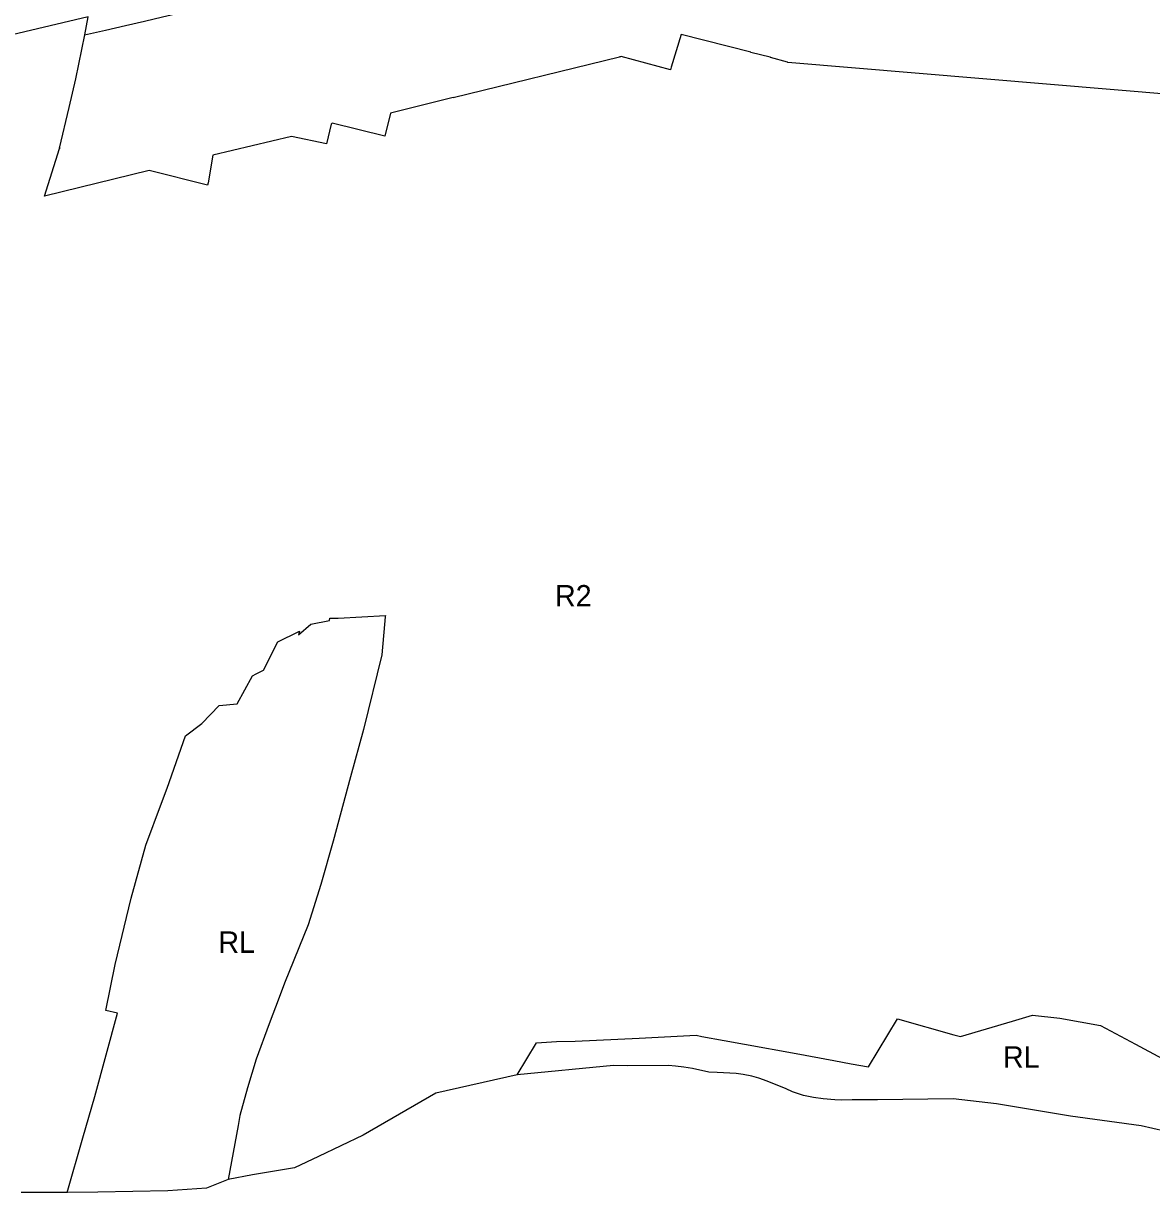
# Model space of a CAD drawing. Extents: x 7413438 to 7416393, y 5541665 to 5544118.
# Drawn here: x 7414625.9 to 7414942.1, y 5541689.3 to 5542017 of the extents above; entities that cross this region are included whole.
import ezdxf

# ---------------------------------------------------------------- set-up
doc = ezdxf.new("R2010")
doc.units = 0
for name, color, linetype in [('linie_rozgraniczajace', 7, 'Continuous'), ('linie_zabudowy_nieprzekraczalne', 7, 'Continuous'), ('oznaczenia_przeznaczen', 7, 'Continuous')]:
    doc.layers.add(name, color=color, linetype=linetype)

msp = doc.modelspace()

# ---------------------------------------------------------------- linework, layer by layer
at = {"layer": 'linie_rozgraniczajace'}
for p, q in [((7414644.1, 5542018.75), (7414622.76, 5542013.76)), ((7414643.15, 5542013.74), (7414644.1, 5542018.75)), ((7414640.59, 5542001.38), (7414643.15, 5542013.74)), ((7414810.29, 5542013.88), (7414807.46, 5542004.7)), ((7414829.75, 5542008.86), (7414810.29, 5542013.88)), ((7414829.81, 5542008.81), (7414829.75, 5542008.86)), ((7414835.19, 5542007.45), (7414829.81, 5542008.81)), ((7414792.96, 5542007.51), (7414746.39, 5541996.13)), ((7414792.97, 5542007.55), (7414792.96, 5542007.51)), ((7414793.21, 5542007.6), (7414792.97, 5542007.55)), ((7414793.42, 5542007.64), (7414793.21, 5542007.6)), ((7414807.26, 5542003.9), (7414793.42, 5542007.64)), ((7414835.27, 5542007.5), (7414835.19, 5542007.45)), ((7414835.25, 5542007.42), (7414835.27, 5542007.5)), ((7414840.03, 5542006.08), (7414835.25, 5542007.42)), ((7414840.1, 5542005.99), (7414840.03, 5542006.08)), ((7414952.51, 5541996.58), (7414840.1, 5542005.99)), ((7414807.46, 5542004.7), (7414807.26, 5542003.9)), ((7414638.8, 5541993.41), (7414640.59, 5542001.38)), ((7414746.36, 5541996.17), (7414728.8, 5541991.78)), ((7414746.39, 5541996.13), (7414746.36, 5541996.17)), ((7414636.1, 5541982.01), (7414638.8, 5541993.41)), ((7414712.48, 5541988.95), (7414712.21, 5541988.7)), ((7414727.19, 5541985.33), (7414712.48, 5541988.95)), ((7414728.8, 5541991.78), (7414727.2, 5541985.38)), ((7414712.21, 5541988.7), (7414710.84, 5541983.2)), ((7414701.02, 5541985.22), (7414679.04, 5541979.99)), ((7414710.84, 5541983.2), (7414701.02, 5541985.22)), ((7414727.2, 5541985.38), (7414727.19, 5541985.33)), ((7414631.88, 5541968.55), (7414636.08, 5541981.92)), ((7414636.08, 5541981.92), (7414636.23, 5541981.98)), ((7414636.23, 5541981.98), (7414636.1, 5541982.01)), ((7414679.04, 5541979.99), (7414677.72, 5541972.23)), ((7414661.15, 5541975.72), (7414631.88, 5541968.55)), ((7414677.54, 5541971.6), (7414661.15, 5541975.72)), ((7414677.72, 5541972.23), (7414677.54, 5541971.6)), ((7414703.06, 5541845.58), (7414706.46, 5541848.54)), ((7414706.46, 5541848.54), (7414711.7, 5541849.6)), ((7414711.7, 5541849.6), (7414711.82, 5541850.21)), ((7414711.82, 5541850.21), (7414714.11, 5541850.3)), ((7414714.11, 5541850.3), (7414727.38, 5541851.03)), ((7414727.09, 5541848.49), (7414726.34, 5541839.99)), ((7414727.28, 5541850.6), (7414727.09, 5541848.49)), ((7414727.38, 5541851.03), (7414727.28, 5541850.6)), ((7414697.25, 5541843.58), (7414703.16, 5541846.48)), ((7414703.3, 5541846.57), (7414703.06, 5541845.58)), ((7414703.16, 5541846.48), (7414703.3, 5541846.57)), ((7414693.22, 5541835.69), (7414697.25, 5541843.58)), ((7414726.34, 5541839.99), (7414721.22, 5541819.07)), ((7414691.13, 5541834.62), (7414693.22, 5541835.69)), ((7414685.88, 5541826.22), (7414690.15, 5541834.12)), ((7414690.15, 5541834.12), (7414691.13, 5541834.62)), ((7414675.97, 5541820.75), (7414680.83, 5541825.78)), ((7414680.83, 5541825.78), (7414685.88, 5541826.22)), ((7414671.38, 5541817.27), (7414675.97, 5541820.75)), ((7414721.22, 5541819.07), (7414717.62, 5541805.81)), ((7414666.23, 5541802.57), (7414671.38, 5541817.26)), ((7414671.38, 5541817.26), (7414671.38, 5541817.27)), ((7414717.62, 5541805.81), (7414712.71, 5541787.72)), ((7414664.67, 5541798.39), (7414666.23, 5541802.57)), ((7414660.27, 5541786.63), (7414664.67, 5541798.39)), ((7414656.18, 5541771.75), (7414660.27, 5541786.63)), ((7414712.71, 5541787.72), (7414709.27, 5541775.57)), ((7414709.27, 5541775.57), (7414705.77, 5541764.34)), ((7414651.64, 5541753.21), (7414656.18, 5541771.75)), ((7414705.77, 5541764.34), (7414699.12, 5541747.92)), ((7414649.07, 5541740.28), (7414651.64, 5541753.21)), ((7414699.12, 5541747.92), (7414697.63, 5541743.94)), ((7414697.63, 5541743.94), (7414694.82, 5541736.51)), ((7414652.3, 5541739.51), (7414649.07, 5541740.28)), ((7414645.97, 5541716.17), (7414652.3, 5541739.51)), ((7414694.82, 5541736.51), (7414691.16, 5541726.64)), ((7414862.71, 5541724.5), (7414870.92, 5541737.95)), ((7414870.92, 5541737.95), (7414886.68, 5541733.51)), ((7414888.52, 5541733), (7414903.06, 5541737.3)), ((7414903.06, 5541737.3), (7414908.72, 5541738.97)), ((7414908.72, 5541738.97), (7414916.37, 5541738.15)), ((7414916.37, 5541738.15), (7414927.76, 5541736.06)), ((7414798.51, 5541732.57), (7414814.5, 5541733.34)), ((7414814.5, 5541733.34), (7414816.07, 5541733.05)), ((7414886.68, 5541733.51), (7414888.52, 5541733)), ((7414927.76, 5541736.06), (7414937.57, 5541730.82)), ((7414764.27, 5541722.27), (7414769.72, 5541731.19)), ((7414769.72, 5541731.19), (7414775.34, 5541731.62)), ((7414775.34, 5541731.62), (7414780.53, 5541731.71)), ((7414780.53, 5541731.71), (7414798.51, 5541732.57)), ((7414816.07, 5541733.05), (7414822.27, 5541731.91)), ((7414822.27, 5541731.91), (7414827.97, 5541730.87)), ((7414827.97, 5541730.87), (7414842.5, 5541728.21)), ((7414937.57, 5541730.82), (7414945.05, 5541726.8)), ((7414691.16, 5541726.64), (7414688.69, 5541718.65)), ((7414842.5, 5541728.21), (7414853.07, 5541726.28)), ((7414791.28, 5541724.84), (7414764.27, 5541722.27)), ((7414795.22, 5541724.76), (7414791.28, 5541724.84)), ((7414806.74, 5541724.86), (7414795.22, 5541724.76)), ((7414808.68, 5541724.71), (7414806.74, 5541724.86)), ((7414811.04, 5541724.44), (7414808.68, 5541724.71)), ((7414813.44, 5541724.02), (7414811.04, 5541724.44)), ((7414817.98, 5541723.03), (7414813.44, 5541724.02)), ((7414853.07, 5541726.28), (7414857.89, 5541725.39)), ((7414857.89, 5541725.39), (7414862.71, 5541724.5)), ((7414764.27, 5541722.27), (7414741.47, 5541717.09)), ((7414820.35, 5541722.95), (7414817.98, 5541723.03)), ((7414825.63, 5541722.66), (7414820.35, 5541722.95)), ((7414827.6, 5541722.35), (7414825.63, 5541722.66)), ((7414830.09, 5541721.88), (7414827.6, 5541722.35)), ((7414832.03, 5541721.36), (7414830.09, 5541721.88)), ((7414834.37, 5541720.46), (7414832.03, 5541721.36)), ((7414839.64, 5541718.3), (7414834.37, 5541720.46)), ((7414688.69, 5541718.65), (7414686.61, 5541710.87)), ((7414741.47, 5541717.09), (7414721.16, 5541705.36)), ((7414841.42, 5541717.48), (7414839.64, 5541718.3)), ((7414844.52, 5541716.45), (7414841.42, 5541717.48)), ((7414642.6, 5541704.56), (7414645.97, 5541716.17)), ((7414847.38, 5541715.92), (7414844.52, 5541716.45)), ((7414850.08, 5541715.53), (7414847.38, 5541715.92)), ((7414853.3, 5541715.22), (7414850.08, 5541715.53)), ((7414855.15, 5541715.16), (7414853.3, 5541715.22)), ((7414858.15, 5541715.22), (7414855.15, 5541715.16)), ((7414865.31, 5541715.25), (7414858.15, 5541715.22)), ((7414886.48, 5541715.51), (7414865.31, 5541715.25)), ((7414898.58, 5541714.09), (7414886.48, 5541715.51)), ((7414919.31, 5541710.72), (7414898.58, 5541714.09)), ((7414686.61, 5541710.87), (7414686.1, 5541708.05)), ((7414939.11, 5541707.99), (7414919.31, 5541710.72)), ((7414686.1, 5541708.05), (7414683.36, 5541692.92)), ((7414948.93, 5541705.71), (7414939.11, 5541707.99)), ((7414638.16, 5541689.25), (7414642.6, 5541704.56)), ((7414721.16, 5541705.36), (7414708.66, 5541699.35)), ((7414708.66, 5541699.35), (7414701.87, 5541696.21)), ((7414690.15, 5541694.21), (7414683.36, 5541692.92)), ((7414701.87, 5541696.21), (7414690.15, 5541694.21)), ((7414683.36, 5541692.92), (7414677.2, 5541690.5)), ((7414638.16, 5541689.25), (7414625.3, 5541689.3)), ((7414646.83, 5541689.39), (7414638.16, 5541689.25)), ((7414666.43, 5541689.75), (7414646.83, 5541689.39)), ((7414677.2, 5541690.5), (7414666.43, 5541689.75))]:
    msp.add_line(p, q, dxfattribs=at)
at = {"layer": 'linie_zabudowy_nieprzekraczalne'}
for points in [[(7414853.84, 5542083.28), (7414835.96, 5542077.96), (7414829.11, 5542074.47), (7414782.42, 5542058.09), (7414742.58, 5542041.09), (7414706.79, 5542027.89), (7414643.1, 5542013.69)], [(7414471.48, 5541968.46), (7414475.51, 5541969.6), (7414513.16, 5541985.19), (7414548.82, 5542000.27), (7414585.9, 5542015.38), (7414619.44, 5542025.72), (7414635.92, 5542030.24)]]:
    msp.add_open_spline(points, degree=3, dxfattribs=at)

# ---------------------------------------------------------------- texts
at = {"layer": 'oznaczenia_przeznaczen'}
for s, p in [('R2', (7414774.91, 5541853.53)), ('RL', (7414680.57, 5541756.45)), ('RL', (7414900.43, 5541724.26))]:
    msp.add_text(s, height=6, dxfattribs=at).set_placement(p)

doc.saveas('drawing.dxf')
